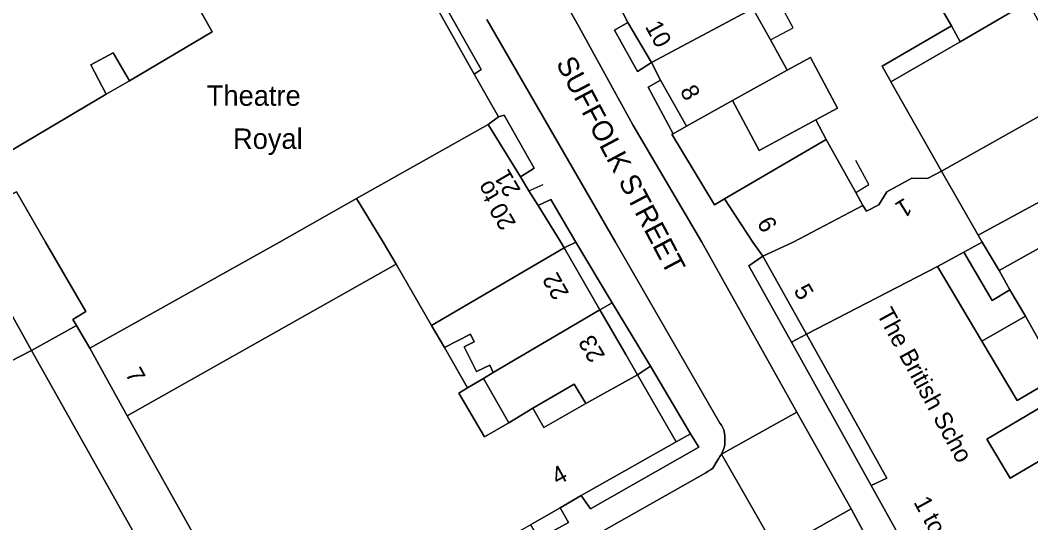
# Model space of a CAD drawing. Extents: x 529240 to 530363, y 179600 to 180767.
# Drawn here: x 529762.1 to 529848.9, y 180475.9 to 180519 of the extents above; entities that cross this region are included whole.
import ezdxf

# ---------------------------------------------------------------- set-up
doc = ezdxf.new("R2010")
doc.units = 0
for name, color, linetype in [('Building', 7, 'Continuous'), ('General surface', 7, 'Continuous'), ('Road Or Track', 7, 'Continuous'), ('Roadside', 7, 'Continuous'), ('Unclassified', 7, 'Continuous')]:
    doc.layers.add(name, color=color, linetype=linetype)

msp = doc.modelspace()

# ---------------------------------------------------------------- linework, layer by layer
at = {"layer": 'Building'}
for points in [[(529841.45, 180531.1), (529838.15, 180529.3), (529836.4, 180528.3), (529842.1, 180518.55), (529842.85, 180517.2), (529848.7, 180520.6), (529852.55, 180522.85), (529847.6, 180534.6)], [(529768.1, 180490.9), (529784.4, 180500), (529791, 180503.75), (529802.3, 180510.1), (529803.2, 180510.75), (529801.1, 180514.4), (529796.3, 180523), (529795.6, 180524.2), (529794.1, 180526.8), (529793.35, 180528.15), (529791.95, 180530.55), (529791.05, 180532.2), (529775.65, 180523.35), (529778.6, 180518.05), (529771.5, 180513.85), (529769.5, 180512.7), (529759.2, 180506.6), (529760.3, 180504.8), (529760.85, 180503.85), (529761.8, 180504.3), (529764.3, 180500), (529767.75, 180494.05), (529766.65, 180493.35), (529766.95, 180492.85)], [(529770.85, 180531.8), (529758.1, 180524.65), (529758.8, 180523.5), (529751.6, 180519.15), (529759.2, 180506.6), (529769.5, 180512.7), (529768.2, 180515.2), (529770.1, 180516.25), (529771.5, 180513.85), (529778.6, 180518.05), (529775.65, 180523.35), (529774.55, 180525.25), (529773.4, 180527.3)], [(529816.35, 180515.4), (529825.05, 180520.05), (529823.65, 180522.6), (529822.2, 180525.15), (529813.5, 180520.4), (529814.3, 180518.85)], [(529823.3, 180512.15), (529828, 180514.75), (529826.55, 180517.35), (529825.05, 180520.05), (529816.35, 180515.4), (529817.1, 180513.9), (529819.35, 180509.95)], [(529841.25, 180506.1), (529853, 180512.7), (529848.7, 180520.6), (529842.85, 180517.2), (529836.9, 180513.75)], [(529842.1, 180518.55), (529836.15, 180515.1), (529836.8, 180513.93), (529836.9, 180513.75), (529842.85, 180517.2)], [(529830.45, 180510.5), (529832.3, 180511.5), (529830, 180515.85), (529828, 180514.75), (529823.3, 180512.15), (529825.6, 180507.85)], [(529818.2, 180509.3), (529818.1, 180509.25), (529821.75, 180503.2), (529822.6, 180503.7), (529831.35, 180508.8), (529830.45, 180510.5), (529825.6, 180507.85), (529823.3, 180512.15), (529819.35, 180509.95)], [(529844.4, 180500.6), (529856.1, 180506.95), (529853, 180512.7), (529841.25, 180506.1)], [(529794.4, 180498.1), (529797.45, 180492.85), (529808.85, 180499.5), (529808.55, 180500), (529806.6, 180503.15), (529805.8, 180504.4), (529805.1, 180505.6), (529802.3, 180510.1), (529791, 180503.75), (529793.3, 180500)], [(529834.5, 180503.15), (529833.9, 180504.25), (529831.35, 180508.8), (529822.6, 180503.7), (529825.05, 180500), (529825.9, 180498.8), (529828.5, 180500)], [(529844.75, 180500), (529846.2, 180497.55), (529850.55, 180500), (529857.85, 180503.8), (529856.1, 180506.95), (529844.4, 180500.6)], [(529834.5, 180503.15), (529828.5, 180500), (529825.9, 180498.8), (529829.65, 180492.1), (529840.9, 180497.9), (529843.15, 180499.15), (529844.75, 180500), (529844.4, 180500.6), (529841.25, 180506.1), (529840.05, 180505.45), (529838.7, 180505.5), (529836.55, 180504.3), (529835.85, 180503.2), (529834.8, 180502.65)], [(529766.95, 180492.85), (529766.65, 180493.35), (529767.75, 180494.05), (529764.3, 180500), (529761.8, 180504.3), (529760.85, 180503.85), (529760.3, 180504.8), (529756.35, 180502.3), (529756.5, 180502.1), (529757.9, 180500), (529763.1, 180490.7)], [(529791, 180503.75), (529784.4, 180500), (529768.1, 180490.9), (529771.3, 180485.1), (529794.4, 180498.1), (529793.3, 180500)], [(529859.3, 180501.05), (529857.85, 180503.8), (529850.55, 180500), (529846.2, 180497.55), (529847.1, 180495.9), (529848.45, 180493.65), (529849.7, 180491.45), (529859.05, 180497), (529857.25, 180500)], [(529847.1, 180495.9), (529846.2, 180497.55), (529844.75, 180500), (529843.15, 180499.15), (529845.6, 180495)], [(529808.85, 180499.5), (529797.45, 180492.85), (529798.55, 180490.95), (529800.8, 180492.1), (529801.1, 180491.45), (529800.25, 180491), (529801.3, 180488.9), (529802.45, 180489.45), (529802.75, 180488.8), (529811.9, 180494.2)], [(529786.55, 180464.75), (529792.25, 180468), (529793.7, 180468.8), (529796.6, 180470.45), (529798.3, 180471.4), (529801.85, 180473.45), (529803.55, 180474.4), (529805.95, 180475.75), (529808.5, 180477.2), (529810.3, 180478.25), (529818.45, 180482.85), (529815.15, 180488.6), (529810.7, 180486.15), (529807.1, 180484.1), (529806.15, 180485.75), (529804.1, 180484.5), (529802, 180483.3), (529799.8, 180487.05), (529800.55, 180487.5), (529798.55, 180490.95), (529797.45, 180492.85), (529794.4, 180498.1), (529771.3, 180485.1), (529783.65, 180463.1)], [(529806.15, 180485.75), (529809.7, 180487.8), (529810.7, 180486.15), (529815.15, 180488.6), (529814.13, 180490.36), (529811.9, 180494.2), (529802.75, 180488.8), (529801.9, 180488.3), (529804.1, 180484.5)], [(529801.9, 180488.3), (529802.75, 180488.8), (529802.45, 180489.45), (529801.3, 180488.9), (529800.25, 180491), (529801.1, 180491.45), (529800.8, 180492.1), (529798.55, 180490.95), (529800.55, 180487.5)]]:
    msp.add_lwpolyline(points, close=True, dxfattribs=at)
for points in [[(529838.15, 180529.3), (529836.4, 180528.3), (529842.1, 180518.55)], [(529771.5, 180513.85), (529778.6, 180518.05), (529775.65, 180523.35)], [(529801.1, 180514.4), (529796.3, 180523)], [(529813.5, 180520.4), (529814.3, 180518.85)], [(529825.05, 180520.05), (529816.35, 180515.4)], [(529825.05, 180520.05), (529826.55, 180517.35)], [(529848.7, 180520.6), (529842.85, 180517.2)], [(529814.3, 180518.85), (529816.35, 180515.4)], [(529842.1, 180518.55), (529842.85, 180517.2)], [(529826.55, 180517.35), (529828, 180514.75)], [(529842.85, 180517.2), (529836.9, 180513.75)], [(529769.5, 180512.7), (529768.2, 180515.2), (529770.1, 180516.25), (529771.5, 180513.85)], [(529816.35, 180515.4), (529817.1, 180513.9)], [(529828, 180514.75), (529830, 180515.85), (529832.3, 180511.5), (529830.45, 180510.5)], [(529823.3, 180512.15), (529828, 180514.75)], [(529769.5, 180512.7), (529771.5, 180513.85)], [(529803.2, 180510.75), (529801.1, 180514.4)], [(529817.1, 180513.9), (529819.35, 180509.95)], [(529836.9, 180513.75), (529841.25, 180506.1)], [(529759.2, 180506.6), (529769.5, 180512.7)], [(529819.35, 180509.95), (529823.3, 180512.15)], [(529830.45, 180510.5), (529825.6, 180507.85), (529823.3, 180512.15)], [(529841.25, 180506.1), (529853, 180512.7)], [(529802.3, 180510.1), (529803.2, 180510.75)], [(529830.45, 180510.5), (529831.35, 180508.8)], [(529791, 180503.75), (529802.3, 180510.1)], [(529805.1, 180505.6), (529802.3, 180510.1)], [(529819.35, 180509.95), (529818.2, 180509.3)], [(529818.2, 180509.3), (529818.1, 180509.25), (529821.75, 180503.2), (529822.6, 180503.7)], [(529831.35, 180508.8), (529822.6, 180503.7)], [(529831.35, 180508.8), (529833.9, 180504.25)], [(529844.4, 180500.6), (529856.1, 180506.95)], [(529834.5, 180503.15), (529834.8, 180502.65), (529835.85, 180503.2), (529836.55, 180504.3), (529838.7, 180505.5), (529840.05, 180505.45), (529841.25, 180506.1)], [(529841.25, 180506.1), (529844.4, 180500.6)], [(529805.8, 180504.4), (529805.1, 180505.6)], [(529766.95, 180492.85), (529766.65, 180493.35), (529767.75, 180494.05), (529764.3, 180500), (529761.8, 180504.3), (529760.85, 180503.85), (529760.3, 180504.8)], [(529806.6, 180503.15), (529805.8, 180504.4)], [(529833.9, 180504.25), (529834.5, 180503.15)], [(529768.1, 180490.9), (529784.4, 180500), (529791, 180503.75)], [(529791, 180503.75), (529793.3, 180500), (529794.4, 180498.1)], [(529822.6, 180503.7), (529825.05, 180500), (529825.9, 180498.8)], [(529857.85, 180503.8), (529850.55, 180500), (529846.2, 180497.55)], [(529808.85, 180499.5), (529808.55, 180500), (529806.6, 180503.15)], [(529825.9, 180498.8), (529828.5, 180500), (529834.5, 180503.15)], [(529763.1, 180490.7), (529757.9, 180500), (529756.5, 180502.1), (529756.35, 180502.3)], [(529844.75, 180500), (529843.15, 180499.15)], [(529844.4, 180500.6), (529844.75, 180500)], [(529846.2, 180497.55), (529844.75, 180500)], [(529808.85, 180499.5), (529797.45, 180492.85)], [(529811.9, 180494.2), (529808.85, 180499.5)], [(529843.15, 180499.15), (529840.9, 180497.9)], [(529771.3, 180485.1), (529794.4, 180498.1)], [(529797.45, 180492.85), (529794.4, 180498.1)], [(529825.9, 180498.8), (529829.65, 180492.1)], [(529851.4, 180488.55), (529847.75, 180486.4), (529844.7, 180491.5), (529840.9, 180497.9), (529829.65, 180492.1), (529836.55, 180479.75), (529835.2, 180479.1), (529838.3, 180473.55), (529839.75, 180474.35), (529843.95, 180466.8), (529843.05, 180466.3), (529847.35, 180458.7), (529848.25, 180459.15), (529852.1, 180452)], [(529840.9, 180497.9), (529829.65, 180492.1)], [(529840.9, 180497.9), (529844.7, 180491.5)], [(529847.1, 180495.9), (529846.2, 180497.55)], [(529848.45, 180493.65), (529847.1, 180495.9)], [(529802.75, 180488.8), (529811.9, 180494.2)], [(529815.15, 180488.6), (529814.13, 180490.36), (529811.9, 180494.2)], [(529763.1, 180490.7), (529766.95, 180492.85)], [(529766.95, 180492.85), (529768.1, 180490.9)], [(529798.55, 180490.95), (529797.45, 180492.85)], [(529849.7, 180491.45), (529848.45, 180493.65)], [(529802.75, 180488.8), (529802.45, 180489.45), (529801.3, 180488.9), (529800.25, 180491), (529801.1, 180491.45), (529800.8, 180492.1), (529798.55, 180490.95)], [(529829.65, 180492.1), (529836.55, 180479.75), (529835.2, 180479.1)], [(529844.7, 180491.5), (529847.75, 180486.4), (529851.4, 180488.55)], [(529768.1, 180490.9), (529771.3, 180485.1)], [(529800.55, 180487.5), (529798.55, 180490.95)], [(529801.9, 180488.3), (529802.75, 180488.8)], [(529815.15, 180488.6), (529810.7, 180486.15)], [(529818.45, 180482.85), (529815.15, 180488.6)], [(529800.55, 180487.5), (529801.9, 180488.3)], [(529801.9, 180488.3), (529804.1, 180484.5)], [(529810.7, 180486.15), (529809.7, 180487.8), (529806.15, 180485.75)], [(529804.1, 180484.5), (529802, 180483.3), (529799.8, 180487.05), (529800.55, 180487.5)], [(529852.35, 180482.8), (529847.15, 180479.75), (529845.15, 180483.1), (529852.15, 180487.25)], [(529858.1, 180477), (529856.4, 180475.95), (529852.35, 180482.8), (529847.15, 180479.75), (529845.15, 180483.1), (529852.15, 180487.25)], [(529810.7, 180486.15), (529807.1, 180484.1), (529806.15, 180485.75)], [(529771.3, 180485.1), (529783.65, 180463.1), (529786.55, 180464.75)], [(529806.15, 180485.75), (529804.1, 180484.5)], [(529810.3, 180478.25), (529818.45, 180482.85)], [(529835.2, 180479.1), (529838.3, 180473.55)], [(529808.5, 180477.2), (529810.3, 180478.25)], [(529805.95, 180475.75), (529808.5, 180477.2)]]:
    msp.add_lwpolyline(points, dxfattribs=at)
at = {"layer": 'General surface'}
msp.add_lwpolyline([(529825.05, 180520.05), (529826.55, 180517.35), (529828, 180514.75), (529830, 180515.85), (529832.3, 180511.5), (529830.45, 180510.5), (529831.35, 180508.8), (529833.9, 180504.25), (529834.5, 180503.15), (529834.8, 180502.65), (529835.85, 180503.2), (529836.55, 180504.3), (529838.7, 180505.5), (529840.05, 180505.45), (529841.25, 180506.1), (529836.9, 180513.75), (529836.8, 180513.93), (529836.15, 180515.1), (529842.1, 180518.55), (529836.4, 180528.3)], dxfattribs=at)
for points in [[(529801.1, 180514.4), (529801.7, 180514.8), (529796.9, 180523.35), (529796.3, 180523)], [(529814.3, 180518.85), (529813.15, 180518.2), (529815.15, 180514.65), (529816.35, 180515.4)], [(529769.5, 180512.7), (529771.5, 180513.85), (529770.1, 180516.25), (529768.2, 180515.2)], [(529819.35, 180509.95), (529817.1, 180513.9), (529816.05, 180513.3), (529818.2, 180509.3)], [(529802.3, 180510.1), (529805.1, 180505.6), (529806.25, 180506.35), (529803.7, 180510.9), (529803.2, 180510.75)], [(529806.6, 180503.15), (529808.55, 180500), (529808.85, 180499.5), (529809.85, 180500), (529807.7, 180503.65)], [(529811.9, 180494.2), (529812.95, 180494.8), (529809.85, 180500), (529808.85, 180499.5)], [(529843.15, 180499.15), (529840.9, 180497.9), (529844.7, 180491.5), (529848.45, 180493.65), (529847.1, 180495.9), (529845.6, 180495)], [(529829.65, 180492.1), (529825.9, 180498.8), (529824.7, 180497.95), (529828.35, 180491.4)], [(529812.95, 180494.8), (529811.9, 180494.2), (529814.13, 180490.36), (529815.15, 180488.6), (529816.25, 180489.35), (529815.25, 180491)], [(529844.7, 180491.5), (529847.75, 180486.4), (529851.4, 180488.55), (529849.7, 180491.45), (529848.45, 180493.65)], [(529828.35, 180491.4), (529835.2, 180479.1), (529836.55, 180479.75), (529829.65, 180492.1)], [(529818.45, 180482.85), (529819.7, 180483.55), (529816.25, 180489.35), (529815.15, 180488.6)], [(529800.55, 180487.5), (529799.8, 180487.05), (529802, 180483.3), (529804.1, 180484.5), (529801.9, 180488.3)], [(529806.15, 180485.75), (529807.1, 180484.1), (529810.7, 180486.15), (529809.7, 180487.8)], [(529858.1, 180477), (529852.15, 180487.25), (529845.15, 180483.1), (529847.15, 180479.75), (529852.35, 180482.8), (529856.4, 180475.95)], [(529810.3, 180478.25), (529811.1, 180477.1), (529820.4, 180482.4), (529819.7, 180483.55), (529818.45, 180482.85)], [(529808.5, 180477.2), (529805.95, 180475.75), (529806.65, 180474.55), (529809.2, 180475.95)]]:
    msp.add_lwpolyline(points, close=True, dxfattribs=at)
at = {"layer": 'Road Or Track'}
for points in [[(529802.2, 180519.1), (529813.25, 180500), (529822.1, 180484.65), (529822.2, 180484.45), (529822.35, 180484.3), (529822.55, 180483.9), (529822.65, 180483.4), (529822.65, 180482.65), (529822.6, 180482.45), (529822.55, 180482.3), (529822.35, 180481.8), (529828.83, 180485.42), (529820.65, 180500), (529814.75, 180510.05), (529810.1, 180518.5), (529808.6, 180521.15)], [(529808.6, 180521.15), (529810.1, 180518.5), (529814.75, 180510.05), (529820.65, 180500), (529828.83, 180485.42)], [(529822.35, 180481.8), (529822.55, 180482.3), (529822.6, 180482.45), (529822.65, 180482.65), (529822.65, 180483.4), (529822.55, 180483.9), (529822.35, 180484.3), (529822.2, 180484.45), (529822.1, 180484.65), (529813.25, 180500), (529802.2, 180519.1)], [(529780.25, 180460.2), (529763.1, 180490.7)], [(529828.83, 180485.42), (529833.48, 180477.11)], [(529827.1, 180473.5), (529822.35, 180481.8), (529822.2, 180481.6), (529822.1, 180481.4), (529821.9, 180481.1), (529821.7, 180480.75), (529821.6, 180480.6), (529821.4, 180480.45), (529821.2, 180480.35), (529821, 180480.2), (529784.7, 180459.7)], [(529822.35, 180481.8), (529822.2, 180481.6), (529822.1, 180481.4), (529821.9, 180481.1), (529821.7, 180480.75), (529821.6, 180480.6), (529821.4, 180480.45), (529821.2, 180480.35), (529821, 180480.2), (529784.7, 180459.7)], [(529845.81, 180454.25), (529833.48, 180477.11)]]:
    msp.add_lwpolyline(points, dxfattribs=at)
for points in [[(529742.45, 180495.1), (529742.41, 180494.46), (529742.32, 180493.99), (529741.98, 180493.46), (529741.59, 180492.93), (529741.19, 180492.61), (529740.2, 180492.15), (529748.4, 180483.15), (529763.1, 180490.7), (529757.9, 180500), (529756.5, 180502.1), (529756.35, 180502.3), (529754.65, 180502.85), (529750.16, 180500)], [(529763.1, 180490.7), (529748.4, 180483.15), (529748.6, 180483.05), (529748.7, 180482.95), (529748.9, 180482.8), (529749.05, 180482.65), (529749.2, 180482.45), (529749.35, 180482.3), (529749.55, 180481.9), (529760.35, 180463.05), (529766.47, 180452.29), (529782.17, 180458.23), (529781.96, 180458.2), (529781.22, 180458.32), (529780.25, 180460.2)], [(529827.1, 180473.5), (529833.48, 180477.11), (529828.83, 180485.42), (529822.35, 180481.8)], [(529827.1, 180473.5), (529827.4, 180473.35), (529827.7, 180473.25), (529827.9, 180473.15), (529828.15, 180472.95), (529828.4, 180472.8), (529828.6, 180472.55), (529828.85, 180472.35), (529829.05, 180472.1), (529829.25, 180471.9), (529829.4, 180471.65), (529841.65, 180449.4), (529846.78, 180452.5), (529845.81, 180454.25), (529833.48, 180477.11)]]:
    msp.add_lwpolyline(points, close=True, dxfattribs=at)
at = {"layer": 'Roadside'}
for points in [[(529796.9, 180523.35), (529801.7, 180514.8), (529801.1, 180514.4), (529803.2, 180510.75), (529803.7, 180510.9), (529806.25, 180506.35), (529805.1, 180505.6), (529805.8, 180504.4), (529806.6, 180503.15), (529807.7, 180503.65), (529809.85, 180500), (529812.95, 180494.8), (529815.25, 180491), (529816.25, 180489.35), (529819.7, 180483.55), (529820.4, 180482.4), (529811.1, 180477.1), (529810.3, 180478.25), (529808.5, 180477.2), (529809.2, 180475.95), (529806.65, 180474.55)], [(529808.6, 180521.15), (529810.1, 180518.5), (529814.75, 180510.05), (529820.65, 180500), (529828.83, 180485.42), (529833.48, 180477.11), (529845.81, 180454.25), (529846.78, 180452.5), (529847.74, 180450.75), (529849.86, 180446.9)], [(529850.85, 180451.05), (529846.9, 180458.4), (529838.3, 180473.55), (529835.2, 180479.1), (529828.35, 180491.4), (529824.7, 180497.95), (529825.9, 180498.8), (529825.05, 180500), (529822.6, 180503.7), (529821.75, 180503.2), (529818.1, 180509.25), (529818.2, 180509.3), (529816.05, 180513.3), (529817.1, 180513.9), (529816.35, 180515.4), (529815.15, 180514.65), (529813.15, 180518.2), (529814.3, 180518.85), (529813.5, 180520.4)], [(529784.7, 180459.7), (529821, 180480.2), (529821.2, 180480.35), (529821.4, 180480.45), (529821.6, 180480.6), (529821.7, 180480.75), (529821.9, 180481.1), (529822.1, 180481.4), (529822.2, 180481.6), (529822.35, 180481.8), (529822.55, 180482.3), (529822.6, 180482.45), (529822.65, 180482.65), (529822.65, 180483.4), (529822.55, 180483.9), (529822.35, 180484.3), (529822.2, 180484.45), (529822.1, 180484.65), (529813.25, 180500), (529802.2, 180519.1)], [(529783.65, 180463.1), (529771.3, 180485.1), (529768.1, 180490.9), (529766.95, 180492.85), (529763.1, 180490.7), (529780.25, 180460.2)]]:
    msp.add_lwpolyline(points, dxfattribs=at)
at = {"layer": 'Unclassified'}
for points in [[(529801.1, 180514.4), (529801.7, 180514.8), (529796.9, 180523.35), (529796.3, 180523)], [(529826.55, 180517.35), (529828.5, 180518.4), (529827.25, 180520.7)], [(529814.3, 180518.85), (529813.15, 180518.2), (529815.15, 180514.65), (529816.35, 180515.4)], [(529836.9, 180513.75), (529836.8, 180513.93), (529836.15, 180515.1), (529842.1, 180518.55)], [(529817.1, 180513.9), (529816.05, 180513.3), (529818.2, 180509.3)], [(529805.1, 180505.6), (529806.25, 180506.35), (529803.7, 180510.9), (529803.2, 180510.75)], [(529833.9, 180504.25), (529835, 180504.95), (529833.9, 180507)], [(529805.8, 180504.4), (529807.05, 180504.95)], [(529809.85, 180500), (529807.7, 180503.65), (529806.6, 180503.15)], [(529809.85, 180500), (529808.85, 180499.5)], [(529812.95, 180494.8), (529809.85, 180500)], [(529847.1, 180495.9), (529845.6, 180495), (529843.15, 180499.15)], [(529828.35, 180491.4), (529824.7, 180497.95), (529825.9, 180498.8)], [(529812.95, 180494.8), (529811.9, 180494.2)], [(529816.25, 180489.35), (529815.25, 180491), (529812.95, 180494.8)], [(529848.45, 180493.65), (529844.7, 180491.5)], [(529829.65, 180492.1), (529828.35, 180491.4)], [(529835.2, 180479.1), (529828.35, 180491.4)], [(529763.1, 180490.7), (529748.4, 180483.15)], [(529816.25, 180489.35), (529815.15, 180488.6)], [(529819.7, 180483.55), (529816.25, 180489.35)], [(529822.35, 180481.8), (529828.83, 180485.42)], [(529810.3, 180478.25), (529811.1, 180477.1), (529820.4, 180482.4), (529819.7, 180483.55)], [(529819.7, 180483.55), (529818.45, 180482.85)], [(529827.1, 180473.5), (529822.35, 180481.8)], [(529806.65, 180474.55), (529809.2, 180475.95), (529808.5, 180477.2)], [(529827.1, 180473.5), (529833.48, 180477.11)]]:
    msp.add_lwpolyline(points, dxfattribs=at)

# ---------------------------------------------------------------- texts
at = {"layer": 'Road Or Track'}
msp.add_text('SUFFOLK STREET', height=1.75, rotation=297.9, dxfattribs=at).set_placement((529808.1, 180515.35))
at = {"layer": 'Unclassified'}
for s, rotation, p in [('10', 298.6, (529815.75, 180518.5)), ('8', 297.3, (529818.75, 180513)), ('21', 120.4, (529805.15, 180504.46)), ('20 to', 120.4, (529804.75, 180501.61)), ('1', 211.7, (529838.1, 180503.85)), ('6', 299.4, (529825.35, 180501.65)), ('22', 119.3, (529809.3, 180495.6)), ('5', 300.3, (529828.5, 180495.85)), ('The British Scho', 298.5, (529835.64, 180493.85)), ('23', 120.2, (529812.4, 180490.25)), ('7', 299.2, (529771.1, 180488.7)), ('4', 28.5, (529808.27, 180479.1)), ('1 to 4', 298.5, (529838.81, 180477.69))]:
    msp.add_text(s, height=1.5, rotation=rotation, dxfattribs=at).set_placement(p)
for s, p in [('Theatre', (529778.15, 180511.7)), ('Royal', (529780.4, 180508))]:
    msp.add_text(s, height=1.75, dxfattribs=at).set_placement(p)

doc.saveas('drawing.dxf')
